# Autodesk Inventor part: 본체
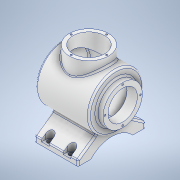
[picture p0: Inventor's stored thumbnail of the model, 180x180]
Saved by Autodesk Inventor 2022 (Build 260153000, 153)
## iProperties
Created: 2023-04
Part Number: 본체
Material: 알루미늄 6061
Document SubType Name: Modeling
Designer: Admin
Mass: 1269.02 g
Surface Area: 1058.92 cm^2
Volume: 470.009 cm^3
Density: 2.7 g/cm^3
Appearance: 알루미늄 - 평지
Author: Admin
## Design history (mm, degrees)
sketch "스케치1"
  geometry: L1 (0, 62)-(10, 62); L2 (10, 62)-(48.324, 7.268); L3 (48.324, 7.268)-(48.324, -7.268); L4 (48.324, -7.268)-(10, -62); L5 (10, -62)-(0, -62); L6 (-51.779, 0)-(65.008, 0) reference; L7 (0, -86.8)-(0, 86.8) reference; L8 (17, 38.5)-(17, -38.5); L9 (0, 62)-(0, 38.5); L10 (0, -38.5)-(0, -62); A1 r 52.096 centre (-35.096, 0) between (0, -38.5) and (0, 38.5); 1 further point
  constraints: 16 end point, 2 point on circle, 2 point on line, 2 vertical, 1 centre point, 1 horizontal, 1 parallel, 1 perpendicular, 1 tangent, 2 other
  dimensions: "d0" = 124 distance between parallel lines of L5 L1; "d2" = 10 distance of L1.start L1.end; "d3" = 10 distance of L4.end L5.end; "d4" = 55 deg angle of L5 L4; "d5" = 55 deg angle of L1 L2; "d6" = 77 distance of L10.start L9.end; "d7" = 17 distance between parallel lines of L10 L8; "d9" = 23.5 distance of L1.start L9.end
extrude "돌출1" new body sketch "스케치1" stored distance "d10" = 80; taper "d11" = 0 deg
sketch "스케치2"
  geometry: L1 (137.042, 77)-(-124.448, 77); L2 (-40, 0)-(40, 0) reference; L3 (0, -15.4)-(0, 92.4) reference; L4 (-48.336, 77)-(48, 77); L5 (48, 77)-(48, 127); L6 (48, 127)-(-48.336, 127); L7 (-48.336, 127)-(-48.336, 77); L8 (-60, 77)-(-60, 148.1); L9 (48, 77)-(60, 77); L10 (60, 77)-(60, 113); L11 (60, 113)-(48, 113); L12 (48, 113)-(48, 77); L13 (40, 48.324)-(40, 10) reference; L14 (60, 77)-(-60, 77); A1 r 113 centre (53, 77) between (-48.336, 127) and (-60, 77); 3 further points
  constraints: 22 end point, 4 parallel, 3 horizontal, 3 point on line, 2 perpendicular, 2 point on circle, 1 centre point, 1 collinear, 1 tangent, 1 vertical
  dimensions: "d13" = 77 distance from line of point (0, 0) L1; "d15" = 100 diameter of L6 L1; "d16" = 20 distance between parallel lines of L13 L10; "d17" = 120 distance between parallel lines of L8 L10; "d18" = 108 distance between parallel lines of L8 L12; "d19" = 72 diameter of L11 L1; "d20" = 226 diameter of A1
revolve "회전1" sketch "스케치2" stored, may be unused: angle "d21" = 90 deg
node "작업 평면1"
sketch "스케치3"
  geometry: L1 (-60, 36)-(-60, -36) reference; C1 r 36 at (2, 0); 1 further point
  constraints: 1 centre point, 1 coincident
  dimensions: "d23" = 72 diameter of C1; "d96" = 62 distance from line of L1 point (2, 0)
extrude "돌출2" join sketch "스케치3" distance "d24" = 65; taper "d25" = 0 deg
feature "쉘2" dims "d31" = 7
sketch "스케치7"
  geometry: L1 (-26.694, 34.722)-(-62, 10) reference; L2 (-62, 10)-(-62, 0) reference; L3 (-62, 0)-(-38.5, 0) reference; L4 (38.5, 0)-(62, 0) reference; L5 (62, 0)-(62, 10) reference; L6 (62, 10)-(26.694, 34.722) reference; A1 r 50 centre (0, 77) between (-26.694, 34.722) and (26.694, 34.722) reference; A2 r 52.096 centre (0, -35.096) between (38.5, 0) and (-38.5, 0) reference; 1 further point
  node "투영된 루프2"
extrude "돌출3" cut sketch "스케치7" extent not by distance; stored distance "d29" = 0; taper "d30" = 0 deg
extrude "돌출4" join sketch "스케치7" distance "d32" = 80; taper "d33" = 0 deg
node "작업 평면2"
sketch "스케치9" dims "d44" = 10
  geometry: L1 (40, -62)-(-40, -62) reference; L2 (40, 62)-(-40, 62) reference; L3 (27, -54)-(27, -62); L4 (13, -54)-(13, -62); L5 (40, -62)-(40, -38.5) reference; L6 (-13, -54)-(-13, -62); L7 (-27, -54)-(-27, -62); L8 (84, 0)-(-84, 0) reference; L9 (13, 54)-(13, 62); L10 (27, 54)-(27, 62); L11 (-13, 54)-(-13, 62); L12 (-27, 54)-(-27, 62); L13 (27, 62)-(13, 62); L14 (-13, 62)-(-27, 62); L15 (27, -62)-(13, -62); L16 (-13, -62)-(-27, -62); A1 r 7 centre (20, -54) between (27, -54) and (13, -54); A2 r 7 centre (-20, -54) between (-13, -54) and (-27, -54); A3 r 7 centre (20, 54) between (27, 54) and (13, 54); A4 r 7 centre (-20, 54) between (-13, 54) and (-27, 54); 7 further points
  constraints: 24 end point, 10 symmetric about line, 8 point on circle, 4 centre point, 3 collinear, 2 perpendicular, 2 point on line, 1 coincident, 1 horizontal, 10 other
  dimensions: "d35" = 20 distance from line of L5 A1.centre; "d36" = 14 distance between parallel lines of L4 L3; "d37" = 14 diameter of A1; "d38" = 8 distance from line of L1 A1.centre; "d41" = 40 distance of A1.centre A2.centre
extrude "돌출5" cut sketch "스케치9" distance "d46" = 30; taper "d47" = 0 deg
sketch "스케치10"
  geometry: L1 (13, -54)-(13, -62) reference; L2 (27, -62)-(13, -62) reference; L3 (27, -62)-(27, -54) reference; L4 (27, 54)-(27, 62) reference; L5 (13, 62)-(27, 62) reference; L6 (13, 62)-(13, 54) reference; A1 r 7 centre (-20, 54) between (-27, 54) and (-13, 54) reference; A2 r 7 centre (-20, -54) between (-13, -54) and (-27, -54) reference; A3 r 7 centre (20, -54) between (27, -54) and (13, -54) reference; A4 r 7 centre (20, 54) between (13, 54) and (27, 54) reference; 5 further points
  constraints: 4 coincident
hole "구멍1" sketch "스케치10" at (-20, -54), (20, -54), (-20, 54), (20, 54) diameter "d48" = 9; stored, may be unused: countersink angle "d52" = 90 deg, drill point angle "d54" = 118 deg; dims "d49" = 6, "d50" = 4, "d51" = 2, "d53" = 8
sketch "스케치11"
  geometry: L1 (0, -105.4)-(0, 93.4) reference; C1 r 36 at (0, 0) reference; 2 further points
  constraints: 1 point on line
  dimensions: "d55" = 32.5 distance of C1.centre point (0, 32.5)
hole "구멍2" sketch "스케치11" at (0, 32.5) diameter "d56" = 3.242; stored, may be unused: countersink angle "d60" = 90 deg, drill point angle "d62" = 118 deg; dims "d57" = 8, "d58" = 4, "d59" = 2, "d61" = 10
sketch "스케치16"
  geometry: C1 r 29 at (0, 0) reference; C2 r 27 at (0, 0); 1 further point
  constraints: 1 centre point, 1 coincident
  dimensions: "d69" = 54 diameter of C2
extrude "돌출7" join sketch "스케치16" distance "d70" = 19; taper "d71" = 0 deg
fillet "모깎기1" dims "d72" = 3
fillet "모깎기2" dims "d73" = 3
sketch "스케치24"
  geometry: L1 (-73, 107)-(-73, 35) reference; 2 further points
  constraints: 1 other
  dimensions: "d92" = 62 distance from line of L1 point (-11, 71); "d93" = 77 vertical distance of point (-13, -6) point (-11, 71)
feature "엠보싱1" sketch "스케치24" dims "d0" = 124, "d2" = 10, "d3" = 10, "d4" = 55 deg, "d5" = 55 deg, "d6" = 77, "d7" = 17, "d9" = 23.5, "d94" = 0.5, "d95" = 0
sketch "스케치25"
  geometry: L1 (0, -93.27)-(0, 97.614); L2 (62, -36)-(62, 36) reference; 2 further points
  constraints: 2 end point, 1 point on line, 1 vertical
  dimensions: "d97" = 62 distance between parallel lines of L2 L1; "d98" = 32.5 vertical distance of point (2, 0) point (0, -32.5)
hole "구멍4" sketch "스케치25" at (0, -32.5) diameter "d99" = 3.242; stored, may be unused: countersink angle "d103" = 90 deg, drill point angle "d105" = 118 deg; dims "d100" = 8, "d101" = 4, "d102" = 2, "d104" = 10
node "솔리드1"
pattern_circular "원형 패턴1" dims angle "d64" = 360 deg
pattern_circular "원형 패턴3" dims angle "d107" = 360 deg
node "투영된 루프3"
node "투영된 루프4"
feature "A9D066F2-1C7D-4E18-AEED-F7BC21143FA4" dims "d48" = 9, "d49" = 6, "d50" = 4, "d51" = 2, "d52" = 90 deg, "d53" = 8, "d54" = 118 deg
other parameters: "d22" = 77, "d34" = 6
